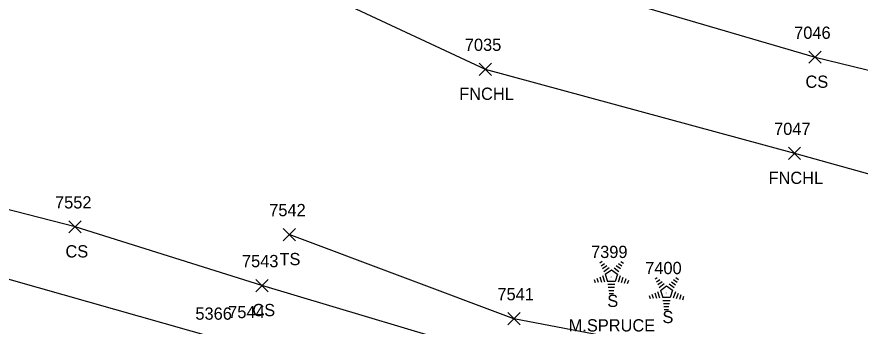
# Model space of a CAD drawing. Extents: x 1505656 to 1508446, y 700805 to 703031.
# Drawn here: x 1507471 to 1507608.7, y 701545.4 to 701595.9 of the extents above; entities that cross this region are included whole.
import ezdxf

# ---------------------------------------------------------------- set-up
doc = ezdxf.new("R2010")
doc.units = 0
for name, color, linetype in [('L_A', 7, 'Continuous'), ('L_C', 7, 'Continuous'), ('L_I', 7, 'Continuous'), ('L_TIC', 7, 'Continuous'), ('LELB', 7, 'Continuous'), ('LFNC', 7, 'Continuous'), ('LTC', 7, 'Continuous')]:
    doc.layers.add(name, color=color, linetype=linetype)

msp = doc.modelspace()

# ---------------------------------------------------------------- linework, layer by layer
at = {"layer": 'L_TIC'}
for points in [[(1507600.29, 701588.31), (1507602.29, 701590.31)], [(1507602.29, 701588.31), (1507600.29, 701590.31)], [(1507546.47, 701586.34), (1507548.47, 701588.34)], [(1507548.47, 701586.34), (1507546.47, 701588.34)], [(1507596.95, 701572.61), (1507598.95, 701574.61)], [(1507598.95, 701572.61), (1507596.95, 701574.61)], [(1507479.52, 701560.6), (1507481.52, 701562.6)], [(1507481.52, 701560.6), (1507479.52, 701562.6)], [(1507514.48, 701559.34), (1507516.48, 701561.34)], [(1507516.48, 701559.34), (1507514.48, 701561.34)], [(1507510.03, 701551.01), (1507512.03, 701553.01)], [(1507512.03, 701551.01), (1507510.03, 701553.01)], [(1507551.15, 701545.6), (1507553.15, 701547.6)], [(1507553.15, 701545.6), (1507551.15, 701547.6)]]:
    msp.add_lwpolyline(points, dxfattribs=at)
at = {"layer": 'LELB'}
for points in [[(1507553.31, 701603.43), (1507601.29, 701589.31), (1507651.17, 701577.15), (1507700.01, 701567.77), (1507706.67, 701566.48), (1507755.13, 701548.25), (1507804.73, 701537.71), (1507857.08, 701521.39), (1507908.09, 701506.28), (1507956.13, 701490.86), (1508006.59, 701471.95), (1508058.56, 701454.54), (1508106.68, 701438.49), (1508127.36, 701424.8)], [(1508002.64, 701414.99), (1507979.81, 701421.48), (1507944.12, 701429.96), (1507890.75, 701447.74), (1507838.58, 701464.8), (1507785.46, 701481.02), (1507746.69, 701489.76), (1507701.55, 701503.96), (1507692.53, 701505.99), (1507687.4, 701507.46), (1507675.9, 701505.41), (1507637.25, 701514.14), (1507591.55, 701528.66), (1507550.69, 701540.13), (1507511.03, 701552.01), (1507480.52, 701561.6), (1507443.25, 701571.18), (1507410.03, 701581.07), (1507381.3, 701588.8), (1507363.75, 701593.74)], [(1507494.24, 701475.49), (1507485.48, 701485.12), (1507482.34, 701502.12), (1507485.56, 701510.11), (1507495.72, 701531.95), (1507503.53, 701543.43), (1507466.09, 701554.03), (1507422.88, 701565.06)], [(1507690.25, 701519.56), (1507678.23, 701514.35), (1507640.03, 701523.8), (1507594.65, 701538.46), (1507552.15, 701546.6), (1507515.48, 701560.34)]]:
    msp.add_lwpolyline(points, dxfattribs=at)
at = {"layer": 'LFNC'}
msp.add_lwpolyline([(1507316.28, 701641.94), (1507325.71, 701640.14), (1507335.33, 701637.87), (1507371.82, 701631.2), (1507412.81, 701624.01), (1507430.26, 701620.91), (1507449.32, 701615.51), (1507500.36, 701609.38), (1507547.47, 701587.34), (1507597.95, 701573.61), (1507645.38, 701560.41), (1507694.84, 701546.04), (1507697.23, 701545.63), (1507701.45, 701546.37), (1507703.46, 701543.53), (1507750.96, 701530.99)], dxfattribs=at)
at = {"layer": 'LTC'}
for p, q in [((1507566.2, 701555.72), (1507566.56, 701555.97)), ((1507569.6, 701555.96), (1507570.02, 701555.65)), ((1507566.41, 701555.25), (1507566.94, 701555.63)), ((1507566.62, 701554.78), (1507567.32, 701555.3)), ((1507566.83, 701554.32), (1507567.71, 701554.96)), ((1507567.06, 701553.86), (1507568.07, 701554.6)), ((1507568.07, 701554.6), (1507569.06, 701553.87)), ((1507568.49, 701554.91), (1507569.3, 701554.32)), ((1507568.86, 701555.26), (1507569.54, 701554.77)), ((1507569.23, 701555.61), (1507569.78, 701555.21)), ((1507565.69, 701553.21), (1507565.9, 701552.56)), ((1507566.15, 701553.43), (1507566.42, 701552.59)), ((1507566.6, 701553.64), (1507566.93, 701552.62)), ((1507567.06, 701553.86), (1507567.44, 701552.67)), ((1507569.06, 701553.87), (1507568.67, 701552.67)), ((1507569.5, 701553.6), (1507569.16, 701552.56)), ((1507569.95, 701553.35), (1507569.66, 701552.47)), ((1507570.39, 701553.1), (1507570.15, 701552.37)), ((1507575.2, 701553.09), (1507575.55, 701553.34)), ((1507578.59, 701553.33), (1507579.01, 701553.02)), ((1507565.23, 701552.99), (1507565.39, 701552.53)), ((1507568.67, 701552.67), (1507567.44, 701552.67)), ((1507568.63, 701552.17), (1507567.49, 701552.17)), ((1507568.55, 701551.67), (1507567.56, 701551.67)), ((1507570.83, 701552.85), (1507570.65, 701552.28)), ((1507575.41, 701552.62), (1507575.94, 701553.01)), ((1507575.62, 701552.16), (1507576.32, 701552.67)), ((1507575.83, 701551.69), (1507576.7, 701552.33)), ((1507576.05, 701551.23), (1507577.06, 701551.97)), ((1507577.06, 701551.97), (1507578.06, 701551.24)), ((1507577.48, 701552.28), (1507578.29, 701551.69)), ((1507577.85, 701552.63), (1507578.53, 701552.14)), ((1507578.22, 701552.98), (1507578.77, 701552.58)), ((1507568.47, 701551.17), (1507567.64, 701551.17)), ((1507568.38, 701550.67), (1507567.71, 701550.67)), ((1507574.23, 701550.37), (1507574.38, 701549.9)), ((1507574.68, 701550.58), (1507574.9, 701549.93)), ((1507575.14, 701550.8), (1507575.41, 701549.96)), ((1507575.6, 701551.02), (1507575.93, 701550)), ((1507576.05, 701551.23), (1507576.44, 701550.04)), ((1507578.06, 701551.24), (1507577.67, 701550.04)), ((1507578.5, 701550.97), (1507578.16, 701549.93)), ((1507578.94, 701550.72), (1507578.65, 701549.84)), ((1507579.39, 701550.47), (1507579.15, 701549.74)), ((1507577.67, 701550.04), (1507576.44, 701550.04)), ((1507577.63, 701549.54), (1507576.48, 701549.54)), ((1507577.55, 701549.04), (1507576.56, 701549.04)), ((1507579.83, 701550.22), (1507579.64, 701549.65)), ((1507577.46, 701548.54), (1507576.63, 701548.54)), ((1507577.38, 701548.04), (1507576.7, 701548.04))]:
    msp.add_line(p, q, dxfattribs=at)

# ---------------------------------------------------------------- texts
at = {"layer": 'L_A'}
for s, p in [('CS', (1507599.73, 701584.31)), ('FNCHL', (1507543.22, 701582.34)), ('FNCHL', (1507593.7, 701568.61)), ('CS', (1507478.96, 701556.6)), ('TS', (1507513.89, 701555.34)), ('S', (1507567.39, 701548.51)), ('CS', (1507509.47, 701547.01)), ('S', (1507576.39, 701545.88))]:
    msp.add_text(s, height=2, dxfattribs=at).set_placement(p)
at = {"layer": 'L_C'}
msp.add_text('M.SPRUCE', height=2, dxfattribs=at).set_placement((1507561.09, 701544.51))
at = {"layer": 'L_I'}
for s, p in [('7046', (1507597.89, 701592.31)), ('7035', (1507544.14, 701590.34)), ('7047', (1507594.61, 701576.61)), ('7552', (1507477.26, 701564.6)), ('7542', (1507512.22, 701563.34)), ('7399', (1507564.74, 701556.51)), ('7543', (1507507.77, 701555.01)), ('7400', (1507573.58, 701553.88)), ('7541', (1507549.46, 701549.6)), ('5366', (1507500.17, 701546.43)), ('7544', (1507505.52, 701546.69))]:
    msp.add_text(s, height=2, dxfattribs=at).set_placement(p)
at = {"layer": 'LTC'}
for p in [(1507567.95, 701553.61), (1507576.94, 701550.98)]:
    msp.add_text('.', height=1.04, rotation=270, dxfattribs=at).set_placement(p)

doc.saveas('drawing.dxf')
